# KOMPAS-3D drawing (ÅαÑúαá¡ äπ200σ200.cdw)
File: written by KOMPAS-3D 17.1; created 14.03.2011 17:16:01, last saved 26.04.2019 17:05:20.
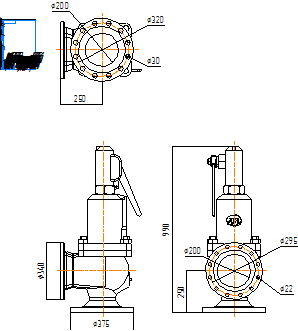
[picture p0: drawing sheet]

Sheet 1: A4, portrait

Title block, sheet 1: name: Прегран Ду200х200; material: Внимание! Данный продукт является объектом авторского права ООО «Торговый Дом АДЛ». / Запрещается изменение, копирование, распространение / (в том числе путем копирования на другие сайты и ресурсы в Интернете) / или любое иное использование информации и объектов без предварительного / согласия правообладателя (ООО «Торговый Дом АДЛ»).; scale: 1:1; sheets: 1; organisation: ООО "Торговый дом АДЛ"; sheet format: A4; stored path: C:\Users\tra\Desktop\2д чертежи\Предохранительные клапаны ПРЕГРАН\ПРЕГРАН 096\ПРЕГРАН КПП 096-03-40\KOMPAS 2D\Прегран Ду200х200.cdw

Views: Спереди 1, Проекционный вид 2, Проекционный вид 3
Dimensions and other numbers on the sheet: 250; 990; 375; 340; 320; 200; 30; 295; 22; 1:1; 1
